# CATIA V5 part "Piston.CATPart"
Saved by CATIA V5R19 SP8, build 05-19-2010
Part number: Piston
Revision: ANY
Definition: UNKNOWN
Nomenclature: 21
Source: Unknown
Bounding box of the stored display mesh (mm): x -66.283 to -50.783, y 0 to 9.5, z -9.5 to 9.5
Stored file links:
  D:\Documents\1_Travail\2- 2I2D\1 - Cours et TD\2- TD\3-TD Assemblage\Pompe AirMan\Piston.CATPart
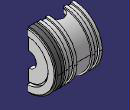
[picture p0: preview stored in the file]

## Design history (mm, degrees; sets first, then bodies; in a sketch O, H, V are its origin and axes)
Set1
  Point1: (-303.2775, 175.673, 11.0647), relative to {point type Center, Curve edge [face of Solid1 | face of Solid1]}
Body1 "Enlèv. mat.-Extru.2" (main body)
  Solid1: solid without history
